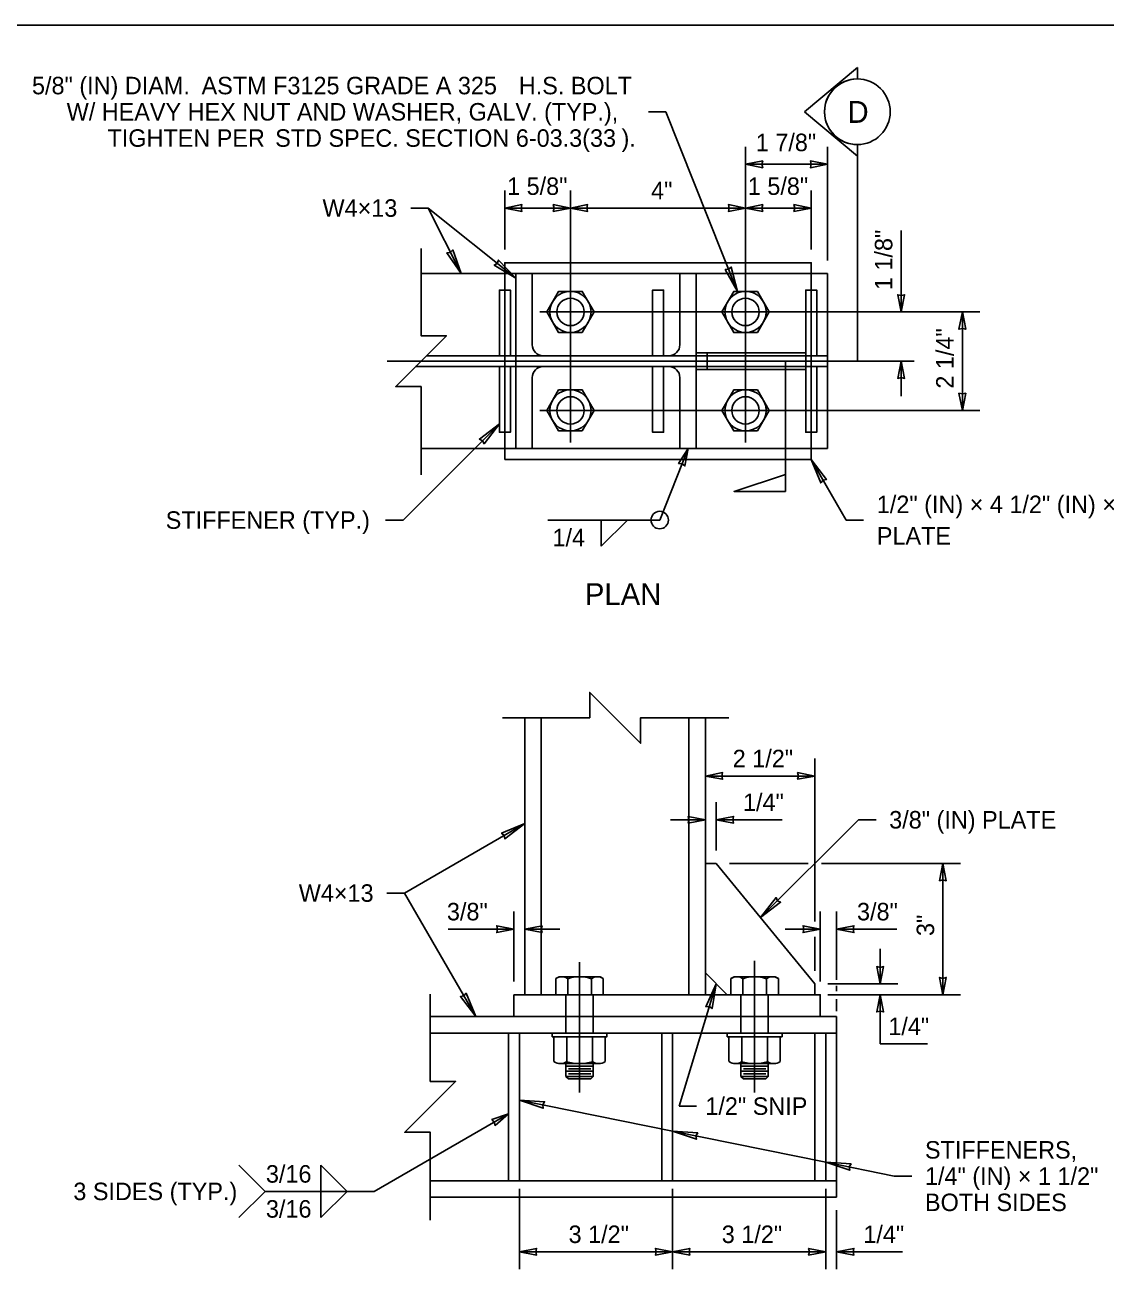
# Model space of a CAD drawing. Extents: x 99862 to 103151, y 100000 to 108076.
# Drawn here: x 101501 to 102488, y 103925 to 105076 of the extents above; entities that cross this region are included whole.
import ezdxf

# ---------------------------------------------------------------- set-up
doc = ezdxf.new("R2010")
doc.units = 0
for name, color, linetype in [('Level 1', 7, 'Continuous'), ('Level 13', 7, 'Continuous'), ('Level 15', 7, 'Continuous'), ('Level 20', 7, 'Continuous'), ('Level 30', 7, 'Continuous'), ('Level 34', 7, 'Continuous'), ('Level 36', 7, 'Continuous'), ('Level 9', 7, 'Continuous')]:
    doc.layers.add(name, color=color, linetype=linetype)

msp = doc.modelspace()

# ---------------------------------------------------------------- linework, layer by layer
at = {"layer": 'Level 1'}
msp.add_lwpolyline([(99862, 102999.5), (103151, 102999.5), (103151, 105075.5), (99862, 105075.5)], close=True, dxfattribs=at)
at = {"layer": 'Level 13'}
for p, q in [((101862.6, 104848.3), (101939.1, 104848.3)), ((101964.1, 104848.3), (101949.1, 104848.3)), ((101949.1, 104848.3), (101949.1, 104688.3)), ((101964.1, 104783.3), (101964.1, 104848.3)), ((102114.1, 104848.3), (102099.1, 104848.3)), ((102099.1, 104848.3), (102099.1, 104783.3)), ((102114.1, 104688.3), (102114.1, 104848.3)), ((102219.1, 104848.3), (102234.1, 104848.3)), ((102234.1, 104848.3), (102234.1, 104688.3)), ((101867.6, 104773.3), (101939.1, 104773.3)), ((102089.1, 104773.3), (101974.1, 104773.3)), ((101857.6, 104763.3), (101939.1, 104763.3)), ((101974.1, 104763.3), (102089.1, 104763.3)), ((101964.1, 104688.3), (101964.1, 104753.3)), ((102099.1, 104753.3), (102099.1, 104688.3)), ((101862.6, 104688.3), (101939.1, 104688.3)), ((101949.1, 104688.3), (101964.1, 104688.3)), ((102099.1, 104688.3), (102114.1, 104688.3)), ((102219.1, 104688.3), (102234.1, 104688.3)), ((101957.4, 104442.3), (101957.4, 104189)), ((101972.4, 104189), (101972.4, 104442.3)), ((102107.4, 104442.3), (102107.4, 104189)), ((102122.4, 104189), (102122.4, 104442.3)), ((102132.4, 104309), (102122.4, 104309)), ((102122.4, 104309), (102122.4, 104209)), ((102222.4, 104199), (102132.4, 104309)), ((102222.4, 104189), (102222.4, 104199)), ((102242.4, 104169), (101870.9, 104169)), ((102242.4, 104169), (102242.4, 104004)), ((101870.9, 104154), (102242.4, 104154)), ((102242.4, 104019), (101870.9, 104019)), ((101870.9, 104004), (102242.4, 104004))]:
    msp.add_line(p, q, dxfattribs=at)
for points in [[(101939.1, 104678.3), (101939.1, 104858.3), (102219.1, 104858.3), (102219.1, 104678.3)], [(102114.1, 104775.8), (102214.1, 104775.8), (102214.1, 104760.8), (102114.1, 104760.8)], [(102114.1, 104775.8), (102124.1, 104775.8), (102124.1, 104760.8), (102114.1, 104760.8)], [(101947.4, 104189), (102227.4, 104189), (102227.4, 104169), (101947.4, 104169)], [(101942.5, 104154), (101952.5, 104154), (101952.5, 104019), (101942.5, 104019)], [(102082.5, 104154), (102092.5, 104154), (102092.5, 104019), (102082.5, 104019)], [(102222.5, 104154), (102232.5, 104154), (102232.5, 104019), (102222.5, 104019)]]:
    msp.add_lwpolyline(points, close=True, dxfattribs=at)
msp.add_lwpolyline([(102122.4, 104209), (102142.4, 104189), (102222.4, 104189)], dxfattribs=at)
for centre, start, end in [((101974.1, 104783.3), 180, 270), ((102089.1, 104783.3), 270, 360), ((101974.1, 104753.3), 90, 180), ((102089.1, 104753.3), 360, 90)]:
    msp.add_arc(centre, 10, start, end, dxfattribs=at)
at = {"layer": 'Level 15'}
for p, q in [((102070.4, 104996.3), (102086.4, 104996.3)), ((102086.4, 104996.3), (102151.2, 104833.2)), ((102159.1, 104964.3), (102159.1, 104694)), ((102234.1, 104860.3), (102234.1, 104964.3)), ((102159.1, 104948.3), (102234.1, 104948.3)), ((101939.1, 104870.3), (101939.1, 104924.3)), ((101999.1, 104924.3), (101999.1, 104694)), ((102219.1, 104870.3), (102219.1, 104924.3)), ((101853.1, 104908.3), (101869.1, 104908.3)), ((101949.1, 104844.1), (101869.1, 104908.3)), ((101869.1, 104908.3), (101899.1, 104848.3)), ((101939.1, 104908.3), (101999.1, 104908.3)), ((101999.1, 104908.3), (102159.1, 104908.3)), ((102159.1, 104908.3), (102219.1, 104908.3)), ((102301.3, 104813.3), (102301.3, 104887.9)), ((102373.2, 104813.3), (101971.2, 104813.3)), ((102357.3, 104813.3), (102357.3, 104723.3)), ((102313.3, 104768.3), (101831.6, 104768.3)), ((102301.3, 104736.3), (102301.3, 104768.3)), ((102373.2, 104723.3), (101971.2, 104723.3)), ((101934.2, 104711), (101846.1, 104623)), ((102106.6, 104688.3), (102080.7, 104623)), ((102219.1, 104678.3), (102251, 104623)), ((101830.1, 104623), (101846.1, 104623)), ((102251, 104623), (102267, 104623)), ((102222.4, 104256.1), (102222.4, 104405)), ((102222.4, 104389), (102122.4, 104389)), ((102132.4, 104321), (102132.4, 104365)), ((101847.4, 104281.9), (101957.4, 104345.5)), ((102090.4, 104349), (102122.4, 104349)), ((102192.7, 104349), (102132.4, 104349)), ((102172.9, 104259.5), (102262.4, 104349)), ((102262.4, 104349), (102278.4, 104349)), ((102144.4, 104309), (102216.4, 104309)), ((102228.4, 104309), (102355.5, 104309)), ((102339.5, 104189), (102339.5, 104309)), ((101831.4, 104281.9), (101847.4, 104281.9)), ((101847.4, 104281.9), (101912.6, 104169)), ((101947.4, 104201), (101947.4, 104265)), ((102227.4, 104201), (102227.4, 104265)), ((102242.4, 104202.5), (102242.4, 104265)), ((101887.2, 104249), (101947.4, 104249)), ((101989.4, 104249), (101957.4, 104249)), ((102195.4, 104249), (102227.4, 104249)), ((102222.4, 104211), (102222.4, 104241.9)), ((102242.4, 104249), (102297.5, 104249)), ((102282.2, 104231), (102282.2, 104199)), ((102007.4, 104218.9), (102007.4, 104099.6)), ((102167.4, 104220.1), (102167.4, 104099.6)), ((102098.4, 104087.2), (102132.4, 104199)), ((102234.4, 104199), (102298.2, 104199)), ((102242.4, 104192.2), (102242.4, 104197.1)), ((102234.4, 104189), (102355.5, 104189)), ((102242.4, 104173.9), (102242.4, 104185.1)), ((102282.2, 104144.1), (102282.2, 104189)), ((102325.5, 104144.1), (102282.2, 104144.1)), ((102092.5, 104064.3), (101952.5, 104092.7)), ((101819.8, 104009.2), (101942.5, 104080)), ((102098.4, 104087.2), (102114.4, 104087.2)), ((102232.5, 104035.9), (102092.5, 104064.3)), ((102295.1, 104023.2), (102232.5, 104035.9)), ((102311.1, 104023.2), (102295.1, 104023.2)), ((101952.5, 104011.5), (101952.5, 103938)), ((102092.5, 104011.5), (102092.5, 103938)), ((102232.5, 104011.5), (102232.5, 103938)), ((102242.4, 103992), (102242.4, 103938)), ((101952.5, 103954), (102092.5, 103954)), ((102092.5, 103954), (102232.5, 103954)), ((102302.7, 103954), (102242.4, 103954))]:
    msp.add_line(p, q, dxfattribs=at)
for points in [[(102159.1, 104948.3), (102174.8, 104945.2), (102174.1, 104948.3), (102174.8, 104951.4)], [(102234.1, 104948.3), (102218.4, 104951.4), (102219.1, 104948.3), (102218.4, 104945.2)], [(101939.1, 104908.3), (101954.8, 104905.2), (101954.1, 104908.3), (101954.8, 104911.4)], [(101999.1, 104908.3), (101983.4, 104911.4), (101984.1, 104908.3), (101983.4, 104905.2)], [(101999.1, 104908.3), (102014.8, 104905.2), (102014.1, 104908.3), (102014.8, 104911.4)], [(102159.1, 104908.3), (102143.4, 104911.4), (102144.1, 104908.3), (102143.4, 104905.2)], [(102159.1, 104908.3), (102174.8, 104905.2), (102174.1, 104908.3), (102174.8, 104911.4)], [(102219.1, 104908.3), (102203.4, 104911.4), (102204.1, 104908.3), (102203.4, 104905.2)], [(101899.1, 104848.3), (101891.5, 104870), (101889.3, 104867.7), (101886.2, 104867.4)], [(101949.1, 104844.1), (101933.2, 104860.7), (101932.1, 104857.7), (101929.4, 104856.1)], [(102151.7, 104832), (102146, 104854.3), (102143.6, 104852.3), (102140.5, 104852.1)], [(102301.3, 104813.3), (102304.4, 104829), (102301.3, 104828.3), (102298.2, 104829)], [(102357.3, 104813.3), (102360.4, 104797.5), (102357.3, 104798.3), (102354.2, 104797.5)], [(102301.3, 104768.3), (102304.4, 104752.5), (102301.3, 104753.3), (102298.2, 104752.5)], [(102357.3, 104723.3), (102360.4, 104739), (102357.3, 104738.3), (102354.2, 104739)], [(101934.2, 104711), (101915.9, 104697), (101918.8, 104695.6), (101920.1, 104692.8)], [(102106.6, 104688.3), (102097.9, 104674.8), (102101.1, 104674.3), (102103.7, 104672.5)], [(102219.1, 104678.3), (102233.1, 104660), (102230, 104659.4), (102227.9, 104657)], [(102122.4, 104389), (102138.2, 104386), (102137.4, 104389), (102138.2, 104392.1)], [(102222.4, 104389), (102206.7, 104392.1), (102207.4, 104389), (102206.7, 104386)], [(101957.4, 104345.5), (101936.2, 104336.7), (101938.6, 104334.6), (101939.2, 104331.5)], [(102122.4, 104349), (102106.7, 104352.1), (102107.4, 104349), (102106.7, 104345.9)], [(102132.4, 104349), (102148.2, 104352.1), (102147.4, 104349), (102148.2, 104345.9)], [(102339.5, 104309), (102342.6, 104293.3), (102339.5, 104294), (102336.4, 104293.3)], [(102172.9, 104259.5), (102191.2, 104273.6), (102188.3, 104274.9), (102187, 104277.8)], [(101947.4, 104249), (101931.7, 104252.1), (101932.4, 104249), (101931.7, 104245.9)], [(101957.4, 104249), (101973.2, 104252.1), (101972.4, 104249), (101973.2, 104245.9)], [(102227.4, 104249), (102211.7, 104252.1), (102212.4, 104249), (102211.7, 104245.9)], [(102242.4, 104249), (102258.2, 104245.9), (102257.4, 104249), (102258.2, 104252.1)], [(102282.2, 104199), (102285.3, 104214.8), (102282.2, 104214), (102279.1, 104214.8)], [(102132.4, 104199), (102122.9, 104178.1), (102126.1, 104178.2), (102128.6, 104176.3)], [(102339.5, 104189), (102342.6, 104204.8), (102339.5, 104204), (102336.4, 104204.8)], [(101912.6, 104169), (101903.7, 104190.3), (101901.7, 104187.9), (101898.6, 104187.3)], [(102282.2, 104189), (102285.3, 104173.3), (102282.2, 104174), (102279.1, 104173.3)], [(101952.5, 104092.7), (101975.5, 104091.1), (101973.8, 104088.4), (101974.3, 104085.3)], [(101942.5, 104080), (101930.4, 104069.5), (101929.5, 104072.5), (101927.3, 104074.8)], [(102092.5, 104064.3), (102115.5, 104062.7), (102113.8, 104060), (102114.3, 104056.9)], [(102232.5, 104035.9), (102255.5, 104034.3), (102253.8, 104031.6), (102254.3, 104028.5)], [(101952.5, 103954), (101968.2, 103951), (101967.5, 103954), (101968.2, 103957.1)], [(102092.5, 103954), (102076.8, 103957.1), (102077.5, 103954), (102076.8, 103951)], [(102092.5, 103954), (102108.2, 103951), (102107.5, 103954), (102108.2, 103957.1)], [(102232.5, 103954), (102216.8, 103957.1), (102217.5, 103954), (102216.8, 103951)], [(102242.4, 103954), (102258.2, 103957.1), (102257.4, 103954), (102258.2, 103951)]]:
    msp.add_lwpolyline(points, close=True, dxfattribs=at)
for points in [[(101862.6, 104871.2), (101862.6, 104791.5), (101885.8, 104791.5), (101839.4, 104745), (101862.6, 104745), (101862.6, 104664.5)], [(101937, 104442.3), (102016.7, 104442.3), (102016.7, 104465.5), (102063.2, 104419), (102063.2, 104442.3), (102143.7, 104442.3)], [(101870.9, 104189.5), (101870.9, 104109.8), (101894.2, 104109.8), (101847.7, 104063.3), (101870.9, 104063.3), (101870.9, 103982.8)]]:
    msp.add_lwpolyline(points, dxfattribs=at)
at = {"layer": 'Level 20'}
for p, q in [((101978.5, 104623), (102080.7, 104623)), ((102027.2, 104623), (102027.2, 104599)), ((102027.2, 104599), (102051.2, 104623)), ((101696, 104033.2), (101720, 104009.2)), ((101771, 104009.2), (101771, 104033.2)), ((101771, 104033.2), (101795, 104009.2)), ((101696, 103985.2), (101720, 104009.2)), ((101720, 104009.2), (101819.8, 104009.2)), ((101771, 104009.2), (101771, 103985.2)), ((101771, 103985.2), (101795, 104009.2))]:
    msp.add_line(p, q, dxfattribs=at)
msp.add_lwpolyline([(102195.6, 104664.7), (102195.6, 104768.3), (102261.3, 104768.3), (102261.3, 104966.3)], dxfattribs=at)
msp.add_circle((102080.7, 104623), 8, dxfattribs=at)
at = {"layer": 'Level 30'}
for p, q in [((101996.6, 104189), (101996.6, 104203.6)), ((102018.3, 104203.6), (102018.3, 104189)), ((102156.6, 104189), (102156.6, 104203.6)), ((102178.3, 104203.6), (102178.3, 104189)), ((101995.7, 104127.9), (101995.7, 104150.6)), ((102019.2, 104150.6), (102019.2, 104127.9)), ((102155.7, 104127.9), (102155.7, 104150.6)), ((102179.2, 104150.6), (102179.2, 104127.9)), ((101989.9, 104126), (102025, 104126)), ((102149.9, 104126), (102185, 104126)), ((101994.9, 104123.7), (102019.9, 104123.7)), ((101994.9, 104119), (102019.9, 104119)), ((102019.9, 104114.3), (101994.9, 104114.3)), ((101997.3, 104121.3), (102017.6, 104121.3)), ((101997.3, 104116.6), (102017.6, 104116.6)), ((102154.9, 104123.7), (102179.9, 104123.7)), ((102154.9, 104119), (102179.9, 104119)), ((102179.9, 104114.3), (102154.9, 104114.3)), ((102157.3, 104121.3), (102177.6, 104121.3)), ((102157.3, 104116.6), (102177.6, 104116.6))]:
    msp.add_line(p, q, dxfattribs=at)
for points in [[(102009.9, 104794.5), (101988.3, 104794.5), (101977.5, 104813.3), (101988.3, 104832), (102009.9, 104832), (102020.8, 104813.3), (102009.9, 104794.5)], [(102169.9, 104794.5), (102148.3, 104794.5), (102137.5, 104813.3), (102148.3, 104832), (102169.9, 104832), (102180.8, 104813.3), (102169.9, 104794.5)], [(102009.9, 104704.5), (101988.3, 104704.5), (101977.5, 104723.3), (101988.3, 104742), (102009.9, 104742), (102020.8, 104723.3), (102009.9, 104704.5)], [(102169.9, 104704.5), (102148.3, 104704.5), (102137.5, 104723.3), (102148.3, 104742), (102169.9, 104742), (102180.8, 104723.3), (102169.9, 104704.5)], [(102026.2, 104205.4), (102029.1, 104203.8), (102029.1, 104189), (101985.8, 104189), (101985.8, 104203.8), (101988.7, 104205.4), (102026.2, 104205.4)], [(102186.2, 104205.4), (102189.1, 104203.8), (102189.1, 104189), (102145.8, 104189), (102145.8, 104203.8), (102148.7, 104205.4), (102186.2, 104205.4)], [(101982.4, 104154), (101982.4, 104150.6), (102032.5, 104150.6), (102032.5, 104154), (101982.4, 104154)], [(102030.9, 104127.9), (102030.9, 104150.6), (101984, 104150.6), (101984, 104127.9)], [(102142.4, 104154), (102142.4, 104150.6), (102192.5, 104150.6), (102192.5, 104154), (102142.4, 104154)], [(102190.9, 104127.9), (102190.9, 104150.6), (102144, 104150.6), (102144, 104127.9)], [(102019.9, 104126), (102019.9, 104114.3), (102017.6, 104112), (101997.3, 104112), (101994.9, 104114.3), (101994.9, 104126)], [(102179.9, 104126), (102179.9, 104114.3), (102177.6, 104112), (102157.3, 104112), (102154.9, 104114.3), (102154.9, 104126)]]:
    msp.add_lwpolyline(points, dxfattribs=at)
for centre in [(101999.1, 104813.3), (102159.1, 104813.3), (101999.1, 104723.3), (102159.1, 104723.3)]:
    msp.add_circle(centre, 18.8, dxfattribs=at)
for centre, radius, start, end in [((101991.1, 104196.3), 9.17, 52.8251, 125.1741), ((102007.4, 104173.1), 32.4, 70.4632, 109.5368), ((102023.8, 104196.3), 9.17, 54.8259, 127.1749), ((102151.1, 104196.3), 9.17, 52.8251, 125.1741), ((102167.4, 104173.1), 32.4, 70.4632, 109.5368), ((102183.8, 104196.3), 9.17, 54.8259, 127.1749), ((101989.9, 104136.2), 10.2, 234.7356, 305.2644), ((102007.4, 104166.6), 40.6, 253.2213, 286.7787), ((102025, 104136.2), 10.2, 234.7356, 305.2644), ((102149.9, 104136.2), 10.2, 234.7356, 305.2644), ((102167.4, 104166.6), 40.6, 253.2213, 286.7787), ((102185, 104136.2), 10.2, 234.7356, 305.2644)]:
    msp.add_arc(centre, radius, start, end, dxfattribs=at)
at = {"layer": 'Level 34'}
for p, q in [((102132.4, 104309), (102122.4, 104309)), ((102122.4, 104309), (102122.4, 104209)), ((102222.4, 104199), (102132.4, 104309)), ((102222.4, 104189), (102222.4, 104199)), ((102189.1, 104189), (102222.4, 104189)), ((102092.5, 104154), (102082.5, 104154)), ((102232.5, 104154), (102222.5, 104154)), ((101942.5, 104019), (101952.5, 104019)), ((102082.5, 104019), (102092.5, 104019)), ((102222.5, 104019), (102232.5, 104019))]:
    msp.add_line(p, q, dxfattribs=at)
msp.add_lwpolyline([(102114.1, 104775.8), (102214.1, 104775.8), (102214.1, 104760.8), (102114.1, 104760.8)], close=True, dxfattribs=at)
for points in [[(102122.4, 104209), (102142.4, 104189), (102145.8, 104189)], [(102147.3, 104204.6), (102148.7, 104205.4), (102150.7, 104205.4)], [(102151.4, 104205.4), (102166.8, 104205.4)], [(102168.1, 104205.4), (102183.5, 104205.4)], [(102184.2, 104205.4), (102186.2, 104205.4)], [(102186.2, 104205.4), (102187.6, 104204.6)], [(102145.8, 104189), (102145.8, 104203.8)], [(102189.1, 104203.8), (102189.1, 104189)], [(101952.5, 104019), (101952.5, 104154), (101942.5, 104154), (101942.5, 104019)], [(102082.5, 104154), (102082.5, 104019)], [(102092.5, 104019), (102092.5, 104154)], [(102222.5, 104154), (102222.5, 104019)], [(102232.5, 104019), (102232.5, 104154)]]:
    msp.add_lwpolyline(points, dxfattribs=at)
for centre, radius, start, end in [((102151.1, 104196.3), 9.17, 87.8478, 92.1522), ((102167.4, 104173.1), 32.4, 88.8545, 91.1455), ((102183.8, 104196.3), 9.17, 87.8478, 92.1522), ((102151.1, 104196.3), 9.17, 114.6481, 125.1741), ((102183.8, 104196.3), 9.17, 54.8259, 65.4796)]:
    msp.add_arc(centre, radius, start, end, dxfattribs=at)
at = {"layer": 'Level 36'}
for p, q in [((102219.1, 104848.3), (101939.1, 104848.3)), ((101939.1, 104773.3), (102234.1, 104773.3)), ((101939.1, 104763.3), (102234.1, 104763.3)), ((101939.1, 104688.3), (102219.1, 104688.3)), ((101994.9, 104154), (101994.9, 104189)), ((102019.9, 104154), (102019.9, 104189)), ((102154.9, 104154), (102154.9, 104189)), ((102179.9, 104154), (102179.9, 104189))]:
    msp.add_line(p, q, dxfattribs=at)
for points in [[(101934.2, 104773.3), (101944.2, 104773.3), (101944.2, 104833.3), (101934.2, 104833.3)], [(102074.2, 104773.3), (102084.2, 104773.3), (102084.2, 104833.3), (102074.2, 104833.3)], [(102214.2, 104773.3), (102224.2, 104773.3), (102224.2, 104833.3), (102214.2, 104833.3)], [(101934.2, 104763.3), (101944.2, 104763.3), (101944.2, 104703.3), (101934.2, 104703.3)], [(102074.2, 104763.3), (102084.2, 104763.3), (102084.2, 104703.3), (102074.2, 104703.3)], [(102214.2, 104763.3), (102224.2, 104763.3), (102224.2, 104703.3), (102214.2, 104703.3)]]:
    msp.add_lwpolyline(points, close=True, dxfattribs=at)
for centre in [(101999.1, 104813.3), (102159.1, 104813.3), (101999.1, 104723.3), (102159.1, 104723.3)]:
    msp.add_circle(centre, 12.5, dxfattribs=at)
at = {"layer": 'Level 9'}
for p, q in [((102261.3, 105036.9), (102212.9, 104996.3)), ((102261.3, 105026.3), (102261.3, 105036.9)), ((102212.9, 104996.3), (102261.3, 104955.7)), ((102261.3, 104955.7), (102261.3, 104966.3)), ((102195.6, 104664.7), (102195.6, 104649.2))]:
    msp.add_line(p, q, dxfattribs=at)
msp.add_lwpolyline([(102195.6, 104664.7), (102148.7, 104649.2), (102195.6, 104649.2)], close=True, dxfattribs=at)
msp.add_circle((102261.3, 104996.3), 30, dxfattribs=at)
msp.add_arc((102261.3, 104996.3), 30, 89.9978, 270.0022, dxfattribs=at)

# ---------------------------------------------------------------- texts
at = {"layer": 'Level 20'}
for s, height, p in [('5/8" (IN) DIAM. ', 16, (101507, 105012.3)), ('ASTM F3125 GRADE A 325 ', 16, (101662, 105012.3)), ('H.S. BOLT ', 16, (101951.9, 105012.3)), ('W/ HEAVY HEX NUT AND WASHER, GALV. (TYP.), ', 16, (101538.7, 104988.3)), ('D', 20, (102252.3, 104986.2)), ('TIGHTEN PER', 16, (101576, 104964.3)), (' STD SPEC. SECTION 6-03.3(33', 16, (101723.3, 104964.3)), (').', 16, (102045.8, 104964.3)), ('1 7/8"', 16, (102168.5, 104960.3)), ('1 5/8"', 16, (101941.2, 104920.3)), ('4"', 16, (102072.8, 104916.3)), ('1 5/8"', 16, (102161.2, 104920.3)), ('W4×13', 16, (101772.5, 104900.3)), ('1/2" (IN) × 4 1/2" (IN) × 7 1/4" (IN)', 16, (102279.1, 104629.4)), ('STIFFENER (TYP.)', 16, (101629.2, 104615)), ('1/4', 16, (101982.7, 104599)), ('PLATE', 16, (102279.1, 104600.6)), ('PLAN', 20, (102012.3, 104545.3)), ('2 1/2"', 16, (102147.4, 104397)), ('1/4"', 16, (102156.8, 104357)), ('3/8" (IN) PLATE', 16, (102290.4, 104341)), ('W4×13', 16, (101750.8, 104274)), ('3/8"', 16, (101886.2, 104257)), ('3/8"', 16, (102261, 104257)), ('1/4"', 16, (102289.6, 104152.1)), ('1/2" SNIP', 16, (102122.4, 104079.2)), ('STIFFENERS,', 16, (102323.1, 104039.2)), ('3/16', 16, (101720.8, 104017.2)), ('1/4" (IN) × 1 1/2"', 16, (102323.1, 104015.2)), ('3 SIDES (TYP.)', 16, (101544.8, 104001.2)), ('3/16', 16, (101720.8, 103985.2)), ('BOTH SIDES', 16, (102323.1, 103991.2)), ('3 1/2"', 16, (101997.4, 103962)), ('3 1/2"', 16, (102137.4, 103962)), ('1/4"', 16, (102266.8, 103962))]:
    msp.add_text(s, height=height, dxfattribs=at).set_placement(p)
for s, p in [('1 1/8"', (102293.3, 104833.3)), ('2 1/4"', (102349.3, 104743.2)), ('3"', (102331.5, 104242.7))]:
    msp.add_text(s, height=16, rotation=90, dxfattribs=at).set_placement(p)

doc.saveas('drawing.dxf')
